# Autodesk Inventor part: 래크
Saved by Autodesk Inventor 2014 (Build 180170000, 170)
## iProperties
Created: 2025-06
Part Number: 래크
Material: 강철, 탄소
Document SubType Name: Modeling
Designer: dg
Density: 7.87 g/cm^3
Appearance: 반연마
Mass: 494.443 g
Surface Area: 157.689 cm^2
Volume: 62.8263 cm^3
Author: jhkim
Creation Date: 2025-05-27
Sending System: Autodesk Inventor 2026
Preprocessor: ST-DEVELOPER v20.1
Author: dg
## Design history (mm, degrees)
node "래크1"
node "솔리드1"
node "기준1"
